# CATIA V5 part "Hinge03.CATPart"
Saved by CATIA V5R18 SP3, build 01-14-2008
Part number: Moving Part Hinge
Bounding box of the stored display mesh (mm): x -29 to 0, y -30 to 30, z 0 to 55
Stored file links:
  E:\#00 CATIA V5 Movie\#03 CATIA V5 Data\#07 KIN\Balance Unit (1)\Hinge03.CATPart
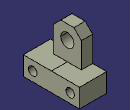
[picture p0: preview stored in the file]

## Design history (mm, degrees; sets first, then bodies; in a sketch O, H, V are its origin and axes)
Body1 (main body)
  Sketch1 on yz-plane, origin (0, 0, 0), H (0, 1, 0), V (0, 0, 1)
    point P1 (0, 20)
    line L1 (0, 20) -> (-30, 20)
    point P2 (-30, 20)
    line L2 (-30, 20) -> (-30, 0)
    point P3 (-30, 0)
    line L3 (-30, 0) -> (0, 0)
    circle A1 centre (-20, 10) radius 4.5
    point P4 (-20, 10)
    point P5 (30, 0)
    point P6 (30, 20)
    point P7 (0, 20)
    point P8 (0, 0)
    line L4 (30, 0) -> (0, 0)
    line L5 (30, 20) -> (30, 0)
    line L6 (0, 20) -> (30, 20)
    circle A2 centre (20, 10) radius 4.5
    length L3 = 30
    length L2 = 20
    radius A1 = 4.5
    distance P4 H = 10
    distance P4 V = 20
    coincidence: P1 V, P3 H, O P8, P1 P7
    horizontal: L1 H, L3 H
    vertical: L2 V
    symmetry: P3 P5 V, P2 P6 V, P1 P7 V, O P8 V, L3 L4 V, L2 L5 V, L1 L6 V, A1 A2 V
  Pad1: profile Sketch1, direction (-1, 0, 0), length 29
  Sketch2 on end face of Pad1, origin (-29, 0, 0), H (0, -1, 0), V (0, 0, 1)
    line L1 (-7, 55) -> (7, 55)
    line L2 (15, 47) -> (15, 20)
    line L3 (15, 20) -> (-15, 20)
    line L4 (-15, 20) -> (-15, 47)
    reference projected line E1 (0, 20) -> (30, 20) from edge [end face of Pad1 | face of Pad1 from Sketch1.L1]
    line L5 (-7, 55) -> (-15, 47)
    point P3 (-7, 55)
    point P4 (-15, 47)
    point P5 (-15, 55)
    line L6 (7, 55) -> (15, 47)
    point P6 (7, 55)
    point P7 (15, 47)
    point P8 (15, 55)
    circle A1 centre (0, 40) radius 7
    point P9 (0, 40)
    distance L1 H = 55
    length L3 = 30
    distance P3 P5 = 8
    distance P4 P5 = 8
    distance P6 P8 = 8 {= Sketch2.distance(P3 P5)}
    distance P7 P8 = 8 {= Sketch2.distance(P4 P5)}
    radius A1 = 7
    distance P9 H = 40
    horizontal: L1 H, L3 H
    vertical: L2 V, L4 V
    symmetry: L2 L4 V
    coincidence: L3 E1, L1 P5, L4 P5, L1 P8, L2 P8, P9 V
  Pad2: profile Sketch2, direction (1, 0, 0), length 12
